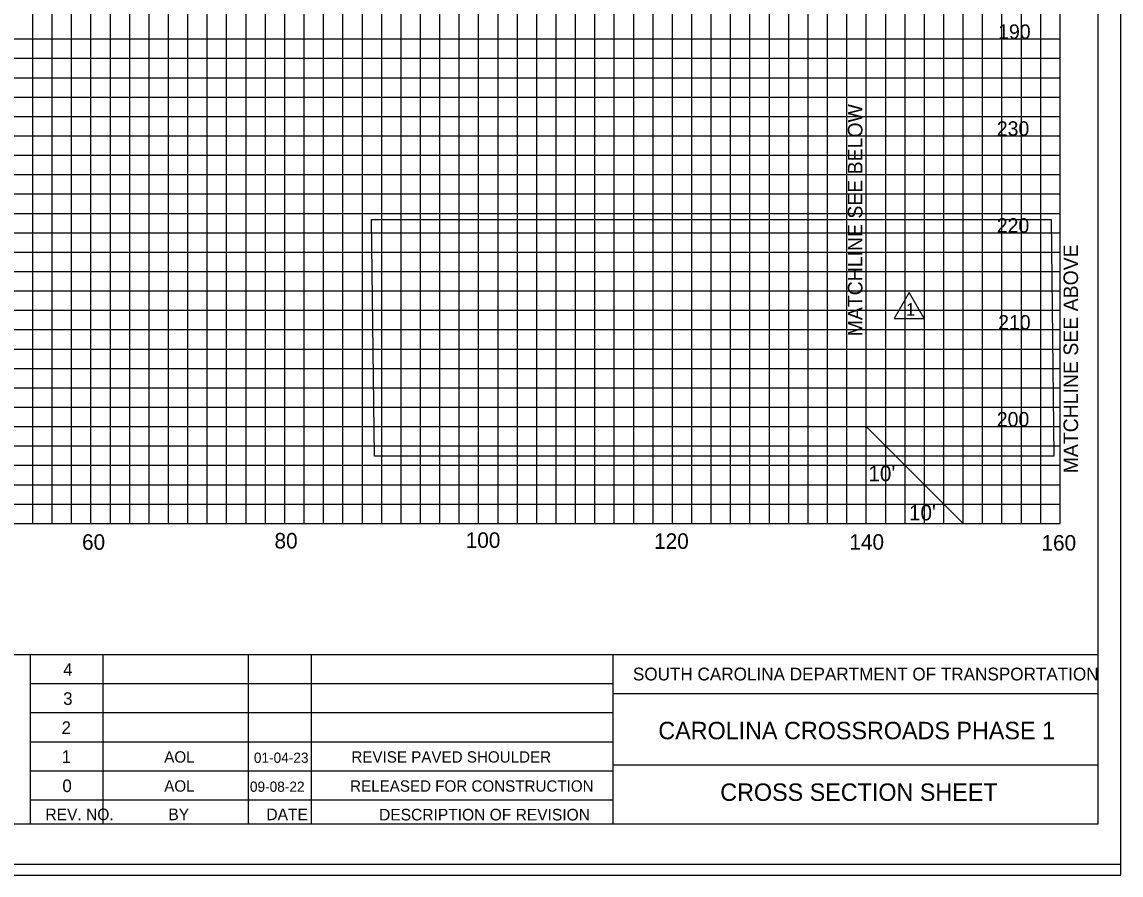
# Model space of a CAD drawing. Extents: x 967 to 1623, y 964 to 7064.
# Drawn here: x 1212.9 to 1326.3, y 4883.7 to 4971.7 of the extents above; entities that cross this region are included whole.
import ezdxf

# ---------------------------------------------------------------- set-up
doc = ezdxf.new("R2010")
doc.units = 0
for name, color, linetype in [('Default', 7, 'Continuous'), ('RD_SHT_Bndy', 7, 'Continuous'), ('RD_SHT_IplotShp', 7, 'Continuous'), ('RD_SHT_Misc1', 7, 'Continuous'), ('RD_SHT_MjGrid', 7, 'Continuous'), ('RD_SHT_MnGrid', 7, 'Continuous'), ('RD_SHT_TX', 7, 'Continuous'), ('RD_Sketch1', 7, 'Continuous'), ('RD_XS_PaveShd', 7, 'Continuous'), ('RD_XS_TX_Station', 7, 'Continuous')]:
    doc.layers.add(name, color=color, linetype=linetype)

msp = doc.modelspace()

# ---------------------------------------------------------------- linework, layer by layer
at = {"layer": 'RD_SHT_Bndy'}
for p, q in [((1323.89, 5098.46), (1323.89, 4888.98)), ((996.11, 4906.49), (1323.89, 4906.49)), ((1213.76, 4888.94), (1213.76, 4906.49)), ((1221.26, 4888.95), (1221.26, 4906.48)), ((1236.26, 4888.95), (1236.26, 4906.48)), ((1242.76, 4888.95), (1242.76, 4906.48)), ((1273.88, 4888.98), (1273.88, 4906.49)), ((1213.76, 4903.48), (1273.88, 4903.48)), ((1323.93, 4902.43), (1273.88, 4902.43)), ((1213.76, 4900.48), (1273.88, 4900.48)), ((1213.76, 4897.48), (1273.88, 4897.48)), ((1323.89, 4895.04), (1273.88, 4895.04)), ((1213.76, 4894.48), (1273.88, 4894.48)), ((1213.76, 4891.48), (1273.88, 4891.48)), ((1323.89, 4888.98), (996.11, 4888.98))]:
    msp.add_line(p, q, dxfattribs=at)
at = {"layer": 'RD_SHT_IplotShp'}
for points in [[(967.41, 4883.72), (1326.28, 4883.72), (1326.28, 5103.72), (967.41, 5103.72)], [(988.52, 4884.84), (1326.28, 4884.84), (1326.28, 5102.6), (988.52, 5102.6)]]:
    msp.add_lwpolyline(points, close=True, dxfattribs=at)
at = {"layer": 'RD_SHT_MjGrid'}
for p, q in [((1220, 4920), (1220, 5090)), ((1230, 4920), (1230, 5090)), ((1240, 4920), (1240, 5090)), ((1250, 4920), (1250, 5090)), ((1260, 4920), (1260, 5090)), ((1270, 4920), (1270, 5090)), ((1280, 4920), (1280, 5090)), ((1290, 4920), (1290, 5090)), ((1300, 4920), (1300, 5090)), ((1310, 4920), (1310, 5090)), ((1320, 4920), (1320, 5090)), ((1000, 4970), (1320, 4970)), ((1000, 4960), (1320, 4960)), ((1000, 4950), (1320, 4950)), ((1000, 4940), (1320, 4940)), ((1000, 4930), (1320, 4930)), ((1000, 4920), (1320, 4920))]:
    msp.add_line(p, q, dxfattribs=at)
at = {"layer": 'RD_SHT_MnGrid'}
for p, q in [((1214, 4920), (1214, 5090)), ((1216, 4920), (1216, 5090)), ((1218, 4920), (1218, 5090)), ((1222, 4920), (1222, 5090)), ((1224, 4920), (1224, 5090)), ((1226, 4920), (1226, 5090)), ((1228, 4920), (1228, 5090)), ((1232, 4920), (1232, 5090)), ((1234, 4920), (1234, 5090)), ((1236, 4920), (1236, 5090)), ((1238, 4920), (1238, 5090)), ((1242, 4920), (1242, 5090)), ((1244, 4920), (1244, 5090)), ((1246, 4920), (1246, 5090)), ((1248, 4920), (1248, 5090)), ((1252, 4920), (1252, 5090)), ((1254, 4920), (1254, 5090)), ((1256, 4920), (1256, 5090)), ((1258, 4920), (1258, 5090)), ((1262, 4920), (1262, 5090)), ((1264, 4920), (1264, 5090)), ((1266, 4920), (1266, 5090)), ((1268, 4920), (1268, 5090)), ((1272, 4920), (1272, 5090)), ((1274, 4920), (1274, 5090)), ((1276, 4920), (1276, 5090)), ((1278, 4920), (1278, 5090)), ((1282, 4920), (1282, 5090)), ((1284, 4920), (1284, 5090)), ((1286, 4920), (1286, 5090)), ((1288, 4920), (1288, 5090)), ((1292, 4920), (1292, 5090)), ((1294, 4920), (1294, 5090)), ((1296, 4920), (1296, 5090)), ((1298, 4920), (1298, 5090)), ((1302, 4920), (1302, 5090)), ((1304, 4920), (1304, 5090)), ((1306, 4920), (1306, 5090)), ((1308, 4920), (1308, 5090)), ((1312, 4920), (1312, 5090)), ((1314, 4920), (1314, 5090)), ((1316, 4920), (1316, 5090)), ((1318, 4920), (1318, 5090)), ((1000, 4968), (1320, 4968)), ((1000, 4966), (1320, 4966)), ((1000, 4964), (1320, 4964)), ((1000, 4962), (1320, 4962)), ((1000, 4958), (1320, 4958)), ((1000, 4956), (1320, 4956)), ((1000, 4954), (1320, 4954)), ((1000, 4952), (1320, 4952)), ((1000, 4948), (1320, 4948)), ((1000, 4946), (1320, 4946)), ((1000, 4944), (1320, 4944)), ((1000, 4942), (1320, 4942)), ((1000, 4938), (1320, 4938)), ((1000, 4936), (1320, 4936)), ((1000, 4934), (1320, 4934)), ((1000, 4932), (1320, 4932)), ((1000, 4928), (1320, 4928)), ((1000, 4926), (1320, 4926)), ((1000, 4924), (1320, 4924)), ((1000, 4922), (1320, 4922))]:
    msp.add_line(p, q, dxfattribs=at)
at = {"layer": 'RD_SHT_TX'}
for p, q in [((1248.95, 4951.37), (1319.06, 4951.37)), ((1249.24, 4926.93), (1248.95, 4951.37)), ((1319.06, 4951.37), (1319.35, 4926.93)), ((1300, 4930), (1310, 4920)), ((1319.35, 4926.93), (1249.24, 4926.93))]:
    msp.add_line(p, q, dxfattribs=at)
msp.add_lwpolyline([(1305.96, 4941.16), (1304.41, 4943.84), (1302.87, 4941.16)], close=True, dxfattribs=at)
at = {"layer": 'RD_Sketch1'}
msp.add_lwpolyline([(967.41, 4883.72), (1326.28, 4883.72), (1326.28, 5103.72), (967.41, 5103.72)], close=True, dxfattribs=at)
at = {"layer": 'RD_XS_PaveShd'}
msp.add_line((1300, 4948.42), (1300, 4949.41), dxfattribs=at)
at = {"layer": 'RD_XS_TX_Station'}
msp.add_line((1300, 4940), (1300, 4960), dxfattribs=at)

# ---------------------------------------------------------------- texts
at = {"layer": 'Default'}
for s, p in [('190', (1313.61, 4970)), ('230', (1313.47, 4960)), ('220', (1313.47, 4950)), ('210', (1313.61, 4940)), ('200', (1313.47, 4930))]:
    msp.add_text(s, height=1.5, dxfattribs=at).set_placement(p)
at = {"layer": 'RD_SHT_Misc1'}
for s, height, p in [('AOL', 1.17, (1227.56, 4895.32)), ('01-04-23', 1.053, (1236.81, 4895.3)), ('REVISE PAVED SHOULDER', 1.17, (1246.87, 4895.32)), ('AOL', 1.17, (1227.56, 4892.32)), ('09-08-22', 1.053, (1236.4, 4892.31)), ('RELEASED FOR CONSTRUCTION', 1.17, (1246.74, 4892.32))]:
    msp.add_text(s, height=height, dxfattribs=at).set_placement(p)
at = {"layer": 'RD_SHT_TX'}
for s, height, p in [('1', 1.3, (1304.09, 4941.44)), ("10'", 1.6, (1300.21, 4924.36)), ("10'", 1.6, (1304.4, 4920.32)), ('60', 1.6, (1219.08, 4917.28)), ('80', 1.6, (1238.94, 4917.42)), ('100', 1.6, (1258.67, 4917.48)), ('120', 1.6, (1278.11, 4917.38)), ('140', 1.6, (1298.26, 4917.29)), ('160', 1.6, (1318.08, 4917.2)), ('4', 1.3, (1217.13, 4904.28)), ('SOUTH CAROLINA DEPARTMENT OF TRANSPORTATION', 1.32, (1275.92, 4903.8)), ('3', 1.3, (1217.13, 4901.28)), ('2', 1.3, (1216.97, 4898.28)), ('1', 1.3, (1216.97, 4895.28)), ('0', 1.3, (1217.05, 4892.28)), ('REV. NO.', 1.2, (1215.3, 4889.38)), ('BY', 1.2, (1227.99, 4889.38)), ('DATE', 1.2, (1238.1, 4889.38)), ('DESCRIPTION OF REVISION', 1.2, (1249.73, 4889.35))]:
    msp.add_text(s, height=height, dxfattribs=at).set_placement(p)
for s, p in [('CAROLINA CROSSROADS PHASE 1', (1278.54, 4897.73)), ('CROSS SECTION SHEET', (1284.93, 4891.37))]:
    msp.add_text(s, height=1.8, rotation=0, dxfattribs=at).set_placement(p)
at = {"layer": 'RD_XS_TX_Station'}
for s, p in [('MATCHLINE SEE BELOW', (1299.6, 4939.31)), ('MATCHLINE SEE ABOVE', (1321.85, 4925.17))]:
    msp.add_text(s, height=1.5, rotation=90, dxfattribs=at).set_placement(p)

doc.saveas('drawing.dxf')
